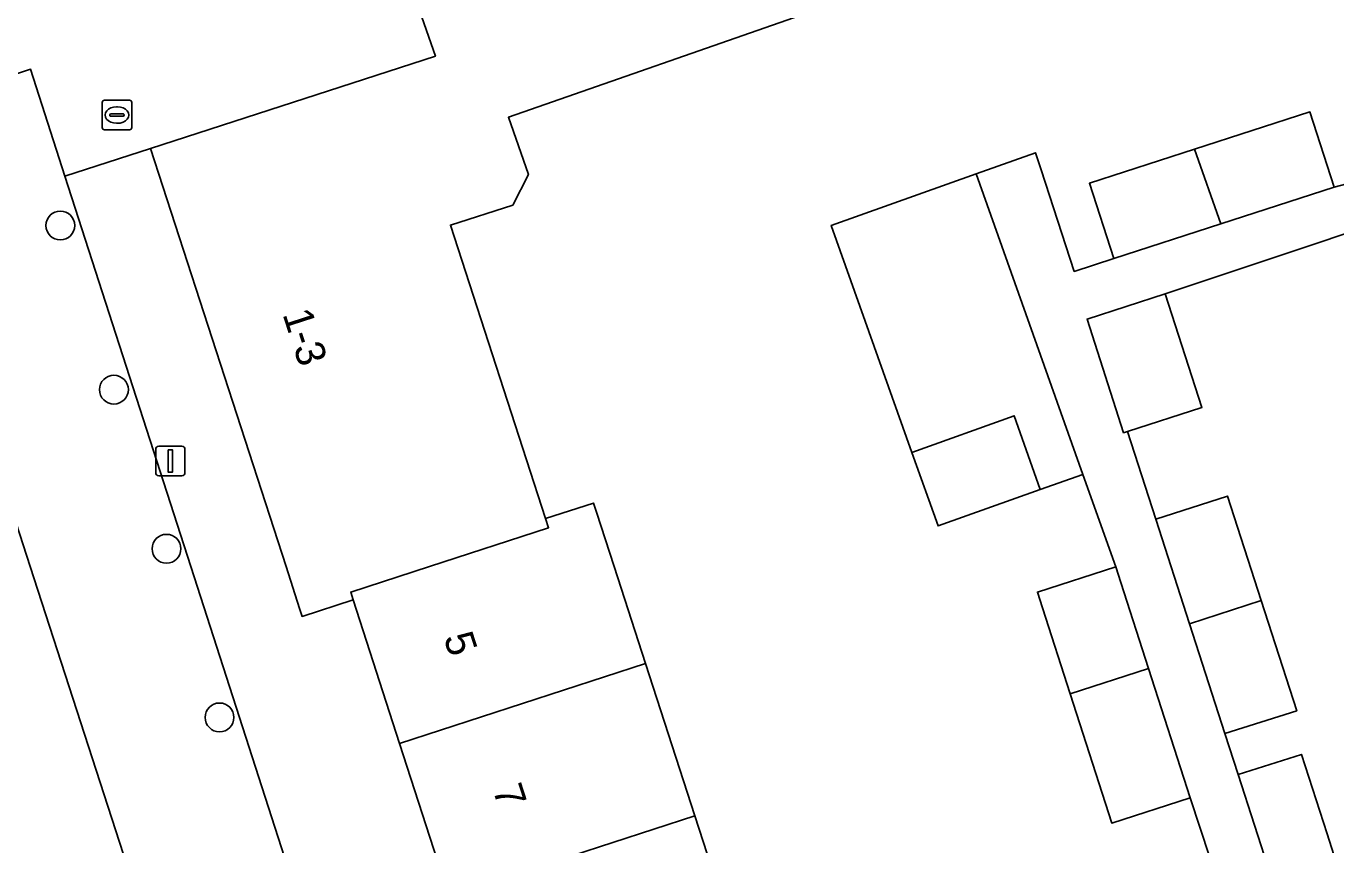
# Model space of a CAD drawing. Extents: x 159371 to 159986, y 382987 to 383597.
# Drawn here: x 159590.67 to 159635.1, y 383240.55 to 383268.33 of the extents above; entities that cross this region are included whole.
import ezdxf

# ---------------------------------------------------------------- set-up
doc = ezdxf.new("R2010")
doc.units = 0
for name, color, linetype in [('IMGEO_Boom', 7, 'Continuous'), ('IMGEO_Brandkraan', 7, 'Continuous'), ('IMGEO_Erf', 7, 'Continuous'), ('IMGEO_Lichtmast', 7, 'Continuous'), ('IMGEO_Pand', 7, 'Continuous'), ('IMGEO_Pand_nummerreeks', 7, 'Continuous'), ('IMGEO_Parkeervlak_open', 7, 'Continuous'), ('IMGEO_Rijbaan_lokaal_open', 7, 'Continuous'), ('IMGEO_Voetpad_open', 7, 'Continuous')]:
    doc.layers.add(name, color=color, linetype=linetype)

msp = doc.modelspace()

# ---------------------------------------------------------------- linework, layer by layer
at = {"layer": 'IMGEO_Boom'}
for centre in [(159591.824, 383261.57), (159593.642, 383256), (159595.425, 383250.6), (159597.225, 383244.877)]:
    msp.add_circle(centre, 0.489, dxfattribs=at)
at = {"layer": 'IMGEO_Brandkraan'}
for p, q in [((159593.244, 383264.892), (159593.244, 383265.744)), ((159593.319, 383265.818), (159594.171, 383265.818)), ((159593.732, 383265.598), (159593.757, 383265.598)), ((159594.245, 383265.744), (159594.245, 383264.892)), ((159593.503, 383265.312), (159593.503, 383265.324)), ((159593.941, 383265.275), (159593.543, 383265.275)), ((159593.546, 383265.361), (159593.944, 383265.361)), ((159593.987, 383265.324), (159593.987, 383265.312)), ((159594.171, 383264.818), (159593.319, 383264.818)), ((159593.755, 383265.038), (159593.73, 383265.038))]:
    msp.add_line(p, q, dxfattribs=at)
for points in [[(159593.244, 383264.892), (159593.244, 383265.744)], [(159593.319, 383265.818), (159594.171, 383265.818)], [(159594.245, 383265.744), (159594.245, 383264.892)], [(159594.171, 383264.818), (159593.319, 383264.818)]]:
    msp.add_lwpolyline(points, dxfattribs=at)
for centre, radius, start, end in [((159593.321, 383265.742), 0.0765, 91.552, 178.448), ((159593.321, 383265.742), 0.0765, 91.552, 178.448), ((159594.169, 383265.742), 0.0765, 1.552, 88.448), ((159594.169, 383265.742), 0.0765, 1.552, 88.448), ((159593.543, 383265.321), 0.0403, 85.8775, 175.7526), ((159593.54, 383265.311), 0.0366, 178.938, 274.7102), ((159593.944, 383265.318), 0.043, 264.8664, 352.4533), ((159593.948, 383265.323), 0.0386, 1.7309, 96.639), ((159593.321, 383264.894), 0.0765, 181.552, 268.448), ((159593.321, 383264.894), 0.0765, 181.552, 268.448), ((159594.169, 383264.894), 0.0765, 271.552, 358.448), ((159594.169, 383264.894), 0.0765, 271.552, 358.448)]:
    msp.add_arc(centre, radius, start, end, dxfattribs=at)
for centre, major_axis, ratio, start_param, end_param in [((159593.731, 383265.318), (-0.387, 0.002), 0.722429, 4.712389, 7.853982), ((159593.756, 383265.318), (-0.39, 0.002), 0.717154, 1.570796, 4.712389)]:
    msp.add_ellipse(centre, major_axis=major_axis, ratio=ratio, start_param=start_param, end_param=end_param, dxfattribs=at)
at = {"layer": 'IMGEO_Erf'}
for points in [[(159638.205, 383274.255), (159633.097, 383272.473), (159627.998, 383270.694), (159622.874, 383268.906), (159622.293, 383270.568), (159617.219, 383268.798), (159607.027, 383265.242), (159607.703, 383263.303), (159607.171, 383262.265), (159605.059, 383261.581), (159608.286, 383251.624), (159609.915, 383252.152), (159610.016, 383251.84), (159610.612, 383250), (159611.68, 383246.704), (159613.353, 383241.539), (159615.036, 383236.346)], [(159631.154, 383239.128), (159630.159, 383242.152), (159627.496, 383241.294), (159626.087, 383245.673), (159625.144, 383248.6), (159624.973, 383249.129), (159627.637, 383249.986), (159626.52, 383253.123), (159625.07, 383252.608), (159621.604, 383251.375), (159620.717, 383253.871), (159617.978, 383261.572), (159622.893, 383263.32), (159624.915, 383264.039), (159625.104, 383263.456), (159626.222, 383260.009), (159627.567, 383260.445), (159626.738, 383263.004), (159630.302, 383264.157), (159634.219, 383265.424), (159635.047, 383262.869), (159637.708, 383263.577)]]:
    msp.add_lwpolyline(points, dxfattribs=at)
msp.add_lwpolyline([(159645.582, 383247.384), (159644.737, 383249.999), (159643.922, 383252.521), (159642.263, 383257.649), (159640.533, 383262.998), (159629.312, 383259.246), (159630.553, 383255.389), (159628.031, 383254.578), (159628.988, 383251.607), (159631.429, 383252.385), (159632.57, 383248.843), (159633.775, 383245.105), (159631.334, 383244.328), (159631.782, 383242.938), (159633.931, 383243.624), (159634.801, 383240.924), (159635.591, 383238.472), (159637.256, 383233.303), (159638.935, 383228.093), (159647.261, 383230.725), (159645.552, 383236.023), (159644.015, 383240.777), (159647.367, 383241.861), (159647.243, 383242.246)], close=True, dxfattribs=at)
at = {"layer": 'IMGEO_Lichtmast'}
for p, q in [((159595.16, 383254.078), (159595.95, 383254.078)), ((159595.95, 383254.078), (159595.16, 383254.078)), ((159595.06, 383253.178), (159595.06, 383253.978)), ((159595.06, 383253.978), (159595.06, 383253.178)), ((159596.05, 383253.978), (159596.05, 383253.178)), ((159596.05, 383253.178), (159596.05, 383253.978)), ((159595.95, 383253.078), (159595.16, 383253.078)), ((159595.16, 383253.078), (159595.95, 383253.078))]:
    msp.add_line(p, q, dxfattribs=at)
msp.add_lwpolyline([(159595.48, 383253.953), (159595.63, 383253.953), (159595.63, 383253.203), (159595.48, 383253.203), (159595.48, 383253.953)], dxfattribs=at)
for centre, start, end in [((159595.16, 383253.978), 90, 180), ((159595.16, 383253.978), 90, 180), ((159595.95, 383253.978), 0, 90), ((159595.95, 383253.978), 360, 90), ((159595.16, 383253.178), 180, 270), ((159595.16, 383253.178), 180, 270), ((159595.95, 383253.178), 270, 0), ((159595.95, 383253.178), 270, 0)]:
    msp.add_arc(centre, 0.1, start, end, dxfattribs=at)
at = {"layer": 'IMGEO_Pand'}
for points in [[(159622.293, 383270.568), (159619.982, 383277.178), (159620.206, 383277.256), (159619.644, 383278.868), (159619.419, 383278.79), (159602.593, 383272.92), (159604.548, 383267.316), (159594.888, 383264.187), (159599.486, 383250), (159599.941, 383248.569), (159600.026, 383248.302), (159601.761, 383248.862), (159601.674, 383249.132), (159604.349, 383250), (159608.387, 383251.311), (159608.286, 383251.624), (159605.059, 383261.581), (159607.171, 383262.265), (159607.703, 383263.303), (159607.027, 383265.242), (159617.219, 383268.798)], [(159630.302, 383264.157), (159631.196, 383261.621), (159635.047, 383262.869), (159634.219, 383265.424)], [(159630.302, 383264.157), (159626.738, 383263.004), (159627.567, 383260.445), (159631.196, 383261.621)], [(159620.717, 383253.871), (159624.187, 383255.114), (159625.07, 383252.608), (159626.52, 383253.123), (159622.893, 383263.32), (159617.978, 383261.572)], [(159629.312, 383259.246), (159626.658, 383258.392), (159627.898, 383254.535), (159628.031, 383254.578), (159630.553, 383255.389)], [(159620.717, 383253.871), (159621.604, 383251.375), (159625.07, 383252.608), (159624.187, 383255.114)], [(159628.988, 383251.607), (159630.133, 383248.054), (159632.57, 383248.843), (159631.429, 383252.385)], [(159610.612, 383250), (159610.016, 383251.84), (159609.915, 383252.152), (159608.286, 383251.624), (159608.387, 383251.311), (159604.349, 383250), (159601.674, 383249.132), (159601.761, 383248.862), (159603.334, 383243.994), (159611.68, 383246.704)], [(159627.807, 383249.457), (159627.637, 383249.986), (159624.973, 383249.129), (159625.144, 383248.6), (159626.087, 383245.673), (159628.747, 383246.537)], [(159632.57, 383248.843), (159630.133, 383248.054), (159631.334, 383244.328), (159633.775, 383245.105)], [(159611.68, 383246.704), (159603.334, 383243.994), (159605.003, 383238.828), (159613.353, 383241.539)], [(159628.747, 383246.537), (159626.087, 383245.673), (159627.496, 383241.294), (159630.159, 383242.152)], [(159631.782, 383242.938), (159633.445, 383237.777), (159635.591, 383238.472), (159634.801, 383240.924), (159633.931, 383243.624)], [(159606.682, 383233.634), (159615.036, 383236.346), (159613.353, 383241.539), (159605.003, 383238.828)]]:
    msp.add_lwpolyline(points, close=True, dxfattribs=at)
at = {"layer": 'IMGEO_Parkeervlak_open'}
for points in [[(159585.361, 383266.81), (159590.799, 383250), (159595.419, 383235.761), (159596.221, 383233.289), (159607.802, 383197.595)], [(159596.25, 383250), (159591.98, 383263.245), (159590.812, 383266.87), (159587.814, 383265.876)], [(159609.174, 383200.07), (159612.043, 383200.997), (159596.25, 383250)]]:
    msp.add_lwpolyline(points, dxfattribs=at)
at = {"layer": 'IMGEO_Rijbaan_lokaal_open'}
msp.add_lwpolyline([(159585.361, 383266.81), (159579.729, 383264.98), (159584.58, 383250), (159589.762, 383233.936), (159595.419, 383235.761), (159590.799, 383250)], close=True, dxfattribs=at)
at = {"layer": 'IMGEO_Voetpad_open'}
for points in [[(159587.814, 383265.876), (159590.812, 383266.87), (159591.98, 383263.245), (159594.888, 383264.187), (159604.548, 383267.316), (159602.593, 383272.92)], [(159606.682, 383233.634), (159605.003, 383238.828), (159603.334, 383243.994), (159601.761, 383248.862), (159600.026, 383248.302), (159599.941, 383248.569), (159599.486, 383250), (159594.888, 383264.187), (159591.98, 383263.245), (159596.25, 383250), (159612.043, 383200.997), (159609.174, 383200.07)], [(159637.708, 383263.577), (159635.047, 383262.869), (159631.196, 383261.621), (159627.567, 383260.445), (159626.222, 383260.009), (159625.104, 383263.456), (159624.915, 383264.039), (159622.893, 383263.32), (159626.52, 383253.123), (159627.637, 383249.986), (159627.807, 383249.457), (159628.747, 383246.537), (159630.159, 383242.152), (159631.154, 383239.128)], [(159633.445, 383237.777), (159631.782, 383242.938), (159631.334, 383244.328), (159630.133, 383248.054), (159628.988, 383251.607), (159628.031, 383254.578), (159627.898, 383254.535), (159626.658, 383258.392), (159629.312, 383259.246), (159640.533, 383262.998)]]:
    msp.add_lwpolyline(points, dxfattribs=at)

# ---------------------------------------------------------------- texts
at = {"layer": 'IMGEO_Pand_nummerreeks'}
for s, rotation, p in [('1-3', 287.9276, (159599.357, 383258.563)), ('5', 287.9105, (159604.82, 383247.59)), ('7', 287.9091, (159606.485, 383242.434))]:
    msp.add_text(s, height=1, rotation=rotation, dxfattribs=at).set_placement(p)

doc.saveas('drawing.dxf')
